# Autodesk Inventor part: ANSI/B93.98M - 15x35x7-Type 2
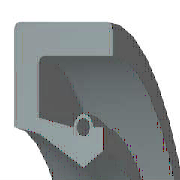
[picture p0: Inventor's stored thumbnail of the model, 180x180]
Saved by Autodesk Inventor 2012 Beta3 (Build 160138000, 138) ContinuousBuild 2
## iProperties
IsCustomPart: 0
Created: 2010-02
Part Number: ANSI/B93.98M - 15x35x7-Type 2
Material: Rubber
Description: Rotary shaft lip type seals 2 - Metal cased
Document SubType Name: Modeling
Standard: ANSI/B93.98M
Designer: Thom Tremblay
Standards Organization: ANSI
Language: en-US
Size Designation: 15x35x7-Type 2
Categories: <MemberInstance><Categories><Category DisplayName="Shaft Parts" InternalName="7f7aeb1f-a693-4053-b835-cee3144e0d98" Mnemonic="SHFT"><Category DisplayName="Seali
Density: 0.93 g/cm^3
Author: Thom Tremblay
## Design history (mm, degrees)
node "WorkPlane2"
node "Sketch1"
node "WorkPoint1"
node "WorkPlane3"
fillet "Fillet1" dims "d38" = 0.4 (= 0.05 x b)
body "Solid1"
revolve "Revolution1" stored, may be unused: angle "d37" = 360 deg
sketch "Sketch2"
  geometry: L1 (15.5, -0.4)-(16.7, -0.4); L2 (15.5, 0)-(15.5, -0.4); L3 (17.5, 0)-(15.5, 0); L4 (17.5, -8)-(17.5, 0); L5 (10.46, -8)-(17.5, -8); L6 (9.21, -4.8)-(10.46, -8); L7 (8.301, -4.251)-(9.21, -4.8); L8 (7.5, -2.2)-(8.301, -4.251); L9 (8.553, -1.2)-(7.5, -2.2); L10 (11.053, -1.2)-(8.553, -1.2); L11 (11.053, -2.2)-(11.053, -1.2); L12 (11.053, -6.4)-(11.053, -3.8); L13 (12.386, -6.4)-(11.053, -6.4); L14 (12.386, -7.2)-(12.386, -6.4); L15 (16.7, -7.2)-(12.386, -7.2); L16 (16.7, -0.4)-(16.7, -7.2); L17 (0, -15.959)-(0, 2.029); L18 (0, -15.959)-(0, 2.029); L19 (0, -19.557)-(0, 5.626) reference; L20 (-5.2, 0)-(31.2, 0) reference; A1 r 0.8 centre (11.053, -3) between (11.053, -3.8) and (11.053, -2.2)
  constraints: 36 end point, 7 vertical, 6 horizontal, 2 collinear, 2 point on circle, 1 centre point, 1 parallel, 1 point on line
  dimensions: "d2" = 0.4 distance of L2.start L1.start (= 0.05 x b); "d4" = 8 distance of L4.start L3.start (= b); "d6" = 0.8 horizontal distance of L1.end L3.start (= 0.1 x b); "d8" = 0.8 horizontal distance of L15.start L4.start (= 0.1 x b); "d10" = 0.8 distance of L14.start L13.start (= 0.1 x b); "d12" = 0.8 vertical distance of L1.end L10.start (= 0.1 x b); "d14" = 1 distance of L11.start L10.start (= 0.125 x b); "d16" = 0.8 radius of A1 (= 0.1 x b); "d18" = 0 horizontal distance of A1.centre L12.end; "d20" = 1 vertical distance of L9.start L8.start (= 0.125 x b); "d22" = 2.05128 vertical distance of L8.start L7.start (= 0.25641 x b); "d24" = 3.2 vertical distance of L6.start L5.start (= 0.4 x b); "d26" = 2 distance of L3.start L2.start (= 0.1 x dd - 0.1 x Diam); "d28" = 1.05263 horizontal distance of L9.start L8.start (= 0.0526316 x dd - 0.0526316 x Diam); "d30" = 2.5 distance of L10.start L9.start (= 0.125 x dd - 0.125 x Diam); "d32" = 1.33333 distance of L13.start L12.start (= 0.0666667 x dd - 0.0666667 x Diam); "d34" = 1.25 horizontal distance of L6.start L5.start (= 0.0625 x dd - 0.0625 x Diam); "d36" = 0.90909 horizontal distance of L7.start L6.start (= 0.0454545 x dd - 0.0454545 x Diam); "msp_d39" = 15 diameter of L8.start L17 (= Diam); "msp_d40" = 35 diameter of L4 L17 (= dd)
other parameters: "dd" = 35 [user parameter; used in 7 equation terms], "Diam" = 15 [user parameter; used in 7 equation terms], "b" = 8 [user parameter; used in 13 equation terms], "d0" = -8 (computed from b), "d1" = 0.4 (derived), "d3" = 8 (derived), "d5" = 0.8 (derived), "d7" = 0.8 (derived), "d9" = 0.8 (derived), "d11" = 0.8 (derived), "d13" = 1 (derived), "d15" = 0.8 (derived), "d17" = 0 (derived), "d19" = 1 (derived), "d21" = 2.05128 (derived), "d23" = 3.2 (derived), "d25" = 2 (derived), "d27" = 1.05263 (derived), "d29" = 2.5 (derived), "d31" = 1.33333 (derived), "d33" = 1.25 (derived), "d35" = 0.90909 (derived), "d42" = 0
